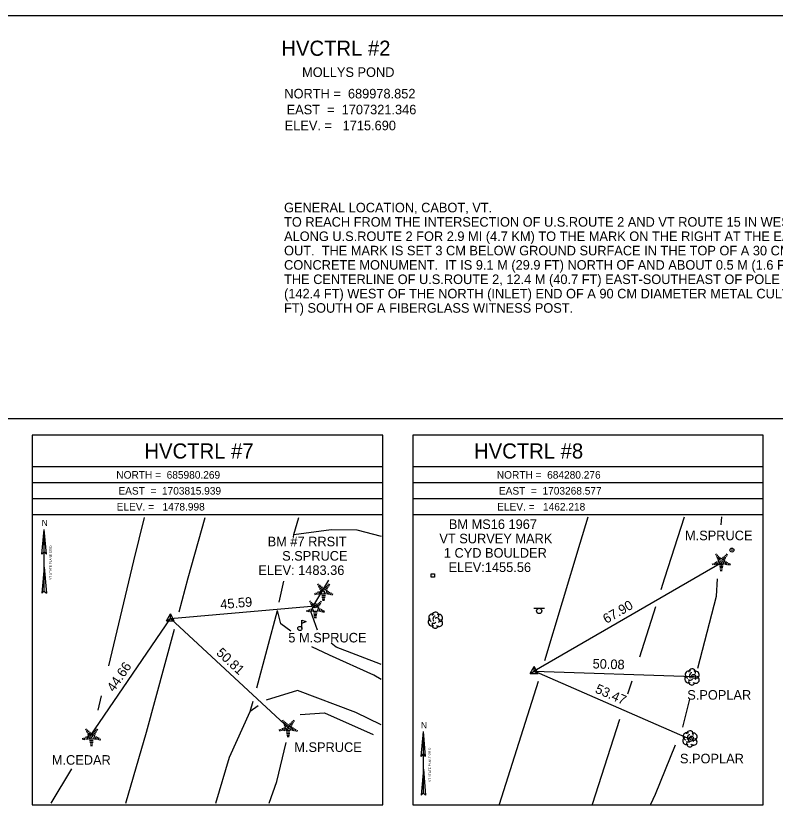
# Model space of a CAD drawing. Extents: x 1702290 to 1703620, y 686233 to 686653.
# Drawn here: x 1702560.6 to 1702798.8, y 686402.8 to 686652.9 of the extents above; entities that cross this region are included whole.
import ezdxf

# ---------------------------------------------------------------- set-up
doc = ezdxf.new("R2010")
doc.units = 0
for name, color, linetype in [('C_C', 7, 'Continuous'), ('CBP', 7, 'Continuous'), ('CPBM', 7, 'Continuous'), ('CPSM', 7, 'Continuous'), ('Default', 7, 'Continuous'), ('L_C', 7, 'Continuous'), ('LAWA', 7, 'Continuous'), ('LMB', 7, 'Continuous'), ('LTC', 7, 'Continuous'), ('LTD', 7, 'Continuous'), ('MPIR', 7, 'Continuous'), ('NBL1', 7, 'Continuous'), ('NBL2', 7, 'Continuous'), ('NNA_P', 7, 'Continuous'), ('PET', 7, 'Continuous'), ('RDG', 7, 'Continuous'), ('RDP', 7, 'Continuous'), ('SSGN', 7, 'Continuous')]:
    doc.layers.add(name, color=color, linetype=linetype)

msp = doc.modelspace()

# ---------------------------------------------------------------- linework, layer by layer
at = {"layer": 'CBP'}
for centre, radius in [((1702782.02, 686481.3), 0.625), ((1702782.02, 686481.3), 0.0833), ((1702654.48, 686467.84), 0.625), ((1702654.48, 686467.84), 0.0833), ((1702773.31, 686445.65), 0.625), ((1702773.31, 686445.65), 0.0833), ((1702646.33, 686429.32), 0.625), ((1702646.33, 686429.32), 0.0833), ((1702583.91, 686426.94), 0.625), ((1702583.91, 686426.94), 0.0833), ((1702772.26, 686425.89), 0.625), ((1702772.26, 686425.89), 0.0833)]:
    msp.add_circle(centre, radius, dxfattribs=at)
at = {"layer": 'CPBM'}
for p, q in [((1702690.96, 686476.81), (1702690.96, 686477.81)), ((1702690.96, 686477.81), (1702691.96, 686477.81)), ((1702691.96, 686477.81), (1702691.96, 686476.81)), ((1702691.96, 686476.81), (1702690.96, 686476.81)), ((1702691.46, 686477.31), (1702691.46, 686477.31)), ((1702691.46, 686477.31), (1702691.46, 686477.31)), ((1702656.32, 686471.5), (1702656.32, 686472.5)), ((1702656.32, 686472.5), (1702657.32, 686472.5)), ((1702657.32, 686471.5), (1702656.32, 686471.5)), ((1702656.83, 686472), (1702656.83, 686472)), ((1702656.83, 686472), (1702656.83, 686472)), ((1702657.32, 686472.5), (1702657.32, 686471.5))]:
    msp.add_line(p, q, dxfattribs=at)
at = {"layer": 'CPSM'}
for p, q in [((1702607.81, 686463.14), (1702609.06, 686465.3)), ((1702610.31, 686463.14), (1702609.06, 686465.3)), ((1702609.06, 686463.86), (1702609.06, 686465.3)), ((1702607.81, 686463.14), (1702609.06, 686463.86)), ((1702607.81, 686463.14), (1702610.31, 686463.14)), ((1702609.06, 686463.86), (1702609.06, 686463.86)), ((1702609.06, 686463.86), (1702610.31, 686463.14)), ((1702722, 686446.56), (1702723.25, 686448.72)), ((1702724.5, 686446.56), (1702723.25, 686448.72)), ((1702723.25, 686447.28), (1702723.25, 686448.72)), ((1702722, 686446.56), (1702723.25, 686447.28)), ((1702722, 686446.56), (1702724.5, 686446.56)), ((1702723.25, 686447.28), (1702723.25, 686447.28)), ((1702723.25, 686447.28), (1702724.5, 686446.56))]:
    msp.add_line(p, q, dxfattribs=at)
at = {"layer": 'Default'}
for p, q in [((1702782.02, 686481.3), (1702723.25, 686447.28)), ((1702609.06, 686463.86), (1702654.48, 686467.84)), ((1702583.91, 686426.94), (1702609.06, 686463.86)), ((1702646.33, 686429.32), (1702609.06, 686463.86)), ((1702723.25, 686447.28), (1702773.31, 686445.65)), ((1702772.26, 686425.89), (1702723.25, 686447.28))]:
    msp.add_line(p, q, dxfattribs=at)
at = {"layer": 'LAWA'}
for points in [[(1702597.61, 686481.91), (1702600.98, 686495.47)], [(1702781.97, 686493.19), (1702782.15, 686495.71)], [(1702589.73, 686448.97), (1702597.61, 686481.91)], [(1702654.04, 686467.99), (1702658.79, 686475.82)], [(1702774.63, 686448.27), (1702780.45, 686470.83), (1702780.82, 686476.26)], [(1702655.29, 686460.14), (1702653.13, 686466.03)], [(1702675.22, 686449.42), (1702675.06, 686449.49), (1702661.06, 686454.83), (1702659.52, 686456.04)], [(1702586.39, 686435.02), (1702587.47, 686439.56)], [(1702769.84, 686429.71), (1702772.12, 686438.57)], [(1702649.79, 686433.68), (1702657.42, 686434.21), (1702672.7, 686427.45)], [(1702640.08, 686405.86), (1702642.46, 686412.67), (1702645.41, 686424.91)], [(1702759.86, 686405.62), (1702761.27, 686408.75), (1702767.6, 686424.22)], [(1702571.67, 686405.86), (1702578.17, 686416.65)]]:
    msp.add_lwpolyline(points, dxfattribs=at)
at = {"layer": 'LMB'}
for p, q in [((1702650.36, 686463.3), (1702651.66, 686462.92)), ((1702650.37, 686460.71), (1702650.37, 686463.3)), ((1702650.37, 686462.4), (1702651.65, 686462.91)), ((1702649.71, 686460.7), (1702649.71, 686460.7))]:
    msp.add_line(p, q, dxfattribs=at)
msp.add_circle((1702649.71, 686460.7), 0.656, dxfattribs=at)
at = {"layer": 'LTC'}
for p, q in [((1702780.09, 686483.85), (1702780.44, 686484.1)), ((1702780.3, 686483.38), (1702780.83, 686483.76)), ((1702780.51, 686482.91), (1702781.21, 686483.43)), ((1702780.72, 686482.45), (1702781.6, 686483.09)), ((1702780.94, 686481.99), (1702781.95, 686482.73)), ((1702781.95, 686482.73), (1702782.95, 686482)), ((1702782.37, 686483.04), (1702783.18, 686482.45)), ((1702782.74, 686483.39), (1702783.42, 686482.9)), ((1702783.12, 686483.74), (1702783.66, 686483.34)), ((1702783.49, 686484.09), (1702783.91, 686483.78)), ((1702779.12, 686481.12), (1702779.27, 686480.66)), ((1702779.58, 686481.34), (1702779.79, 686480.69)), ((1702780.03, 686481.56), (1702780.3, 686480.72)), ((1702780.49, 686481.77), (1702780.82, 686480.76)), ((1702780.94, 686481.99), (1702781.33, 686480.8)), ((1702782.56, 686480.8), (1702781.33, 686480.8)), ((1702782.52, 686480.3), (1702781.38, 686480.3)), ((1702782.95, 686482), (1702782.56, 686480.8)), ((1702783.39, 686481.73), (1702783.05, 686480.69)), ((1702783.83, 686481.48), (1702783.54, 686480.6)), ((1702784.28, 686481.23), (1702784.04, 686480.5)), ((1702784.72, 686480.98), (1702784.53, 686480.41)), ((1702782.44, 686479.8), (1702781.45, 686479.8)), ((1702782.35, 686479.3), (1702781.52, 686479.3)), ((1702782.27, 686478.8), (1702781.59, 686478.8)), ((1702655.29, 686474.48), (1702655.64, 686474.74)), ((1702655.5, 686474.01), (1702656.03, 686474.4)), ((1702655.71, 686473.55), (1702656.41, 686474.06)), ((1702655.92, 686473.08), (1702656.79, 686473.72)), ((1702656.14, 686472.63), (1702657.15, 686473.36)), ((1702657.15, 686473.36), (1702658.15, 686472.64)), ((1702657.57, 686473.68), (1702658.38, 686473.09)), ((1702657.94, 686474.02), (1702658.62, 686473.53)), ((1702658.31, 686474.37), (1702658.86, 686473.97)), ((1702658.69, 686474.72), (1702659.1, 686474.42)), ((1702654.32, 686471.76), (1702654.47, 686471.29)), ((1702654.77, 686471.98), (1702654.99, 686471.32)), ((1702655.23, 686472.19), (1702655.5, 686471.36)), ((1702655.69, 686472.41), (1702656.02, 686471.39)), ((1702656.14, 686472.63), (1702656.53, 686471.43)), ((1702657.76, 686471.43), (1702656.53, 686471.43)), ((1702657.72, 686470.93), (1702656.57, 686470.93)), ((1702657.64, 686470.43), (1702656.65, 686470.43)), ((1702658.15, 686472.64), (1702657.76, 686471.43)), ((1702658.59, 686472.37), (1702658.25, 686471.33)), ((1702659.03, 686472.12), (1702658.74, 686471.23)), ((1702659.48, 686471.87), (1702659.24, 686471.14)), ((1702659.92, 686471.62), (1702659.73, 686471.04)), ((1702652.7, 686469.08), (1702653.06, 686469.33)), ((1702652.91, 686468.61), (1702653.44, 686469)), ((1702653.12, 686468.15), (1702653.83, 686468.66)), ((1702653.33, 686467.68), (1702654.21, 686468.32)), ((1702653.56, 686467.22), (1702654.57, 686467.96)), ((1702654.57, 686467.96), (1702655.57, 686467.23)), ((1702654.99, 686468.27), (1702655.8, 686467.68)), ((1702655.36, 686468.62), (1702656.04, 686468.13)), ((1702655.73, 686468.97), (1702656.28, 686468.57)), ((1702656.1, 686469.32), (1702656.52, 686469.01)), ((1702657.55, 686469.93), (1702656.72, 686469.93)), ((1702657.47, 686469.43), (1702656.79, 686469.43)), ((1702651.74, 686466.36), (1702651.89, 686465.89)), ((1702652.19, 686466.57), (1702652.4, 686465.92)), ((1702652.65, 686466.79), (1702652.92, 686465.95)), ((1702653.1, 686467.01), (1702653.43, 686465.99)), ((1702653.56, 686467.22), (1702653.95, 686466.03)), ((1702655.18, 686466.03), (1702653.95, 686466.03)), ((1702655.14, 686465.53), (1702653.99, 686465.53)), ((1702655.57, 686467.23), (1702655.18, 686466.03)), ((1702656, 686466.96), (1702655.67, 686465.92)), ((1702656.45, 686466.71), (1702656.16, 686465.83)), ((1702656.89, 686466.46), (1702656.66, 686465.73)), ((1702657.34, 686466.21), (1702657.15, 686465.64)), ((1702655.05, 686465.03), (1702654.07, 686465.03)), ((1702654.97, 686464.53), (1702654.14, 686464.53)), ((1702654.89, 686464.03), (1702654.21, 686464.03)), ((1702644.18, 686431.7), (1702644.53, 686431.96)), ((1702644.38, 686431.23), (1702644.91, 686431.62)), ((1702644.59, 686430.77), (1702645.3, 686431.28)), ((1702644.8, 686430.3), (1702645.68, 686430.94)), ((1702645.03, 686429.85), (1702646.04, 686430.58)), ((1702646.04, 686430.58), (1702647.04, 686429.86)), ((1702646.46, 686430.89), (1702647.27, 686430.31)), ((1702646.83, 686431.24), (1702647.51, 686430.75)), ((1702647.2, 686431.59), (1702647.75, 686431.19)), ((1702647.57, 686431.94), (1702647.99, 686431.64)), ((1702582.45, 686428.97), (1702582.81, 686429.23)), ((1702582.66, 686428.5), (1702583.19, 686428.89)), ((1702582.87, 686428.04), (1702583.57, 686428.55)), ((1702583.08, 686427.57), (1702583.96, 686428.21)), ((1702583.31, 686427.12), (1702584.32, 686427.85)), ((1702584.32, 686427.85), (1702585.31, 686427.13)), ((1702584.74, 686428.16), (1702585.55, 686427.57)), ((1702585.11, 686428.51), (1702585.79, 686428.02)), ((1702585.48, 686428.86), (1702586.03, 686428.46)), ((1702585.85, 686429.21), (1702586.27, 686428.9)), ((1702643.21, 686428.98), (1702643.36, 686428.51)), ((1702643.66, 686429.2), (1702643.87, 686428.54)), ((1702644.12, 686429.41), (1702644.39, 686428.58)), ((1702644.57, 686429.63), (1702644.9, 686428.61)), ((1702645.03, 686429.85), (1702645.42, 686428.65)), ((1702646.65, 686428.65), (1702645.42, 686428.65)), ((1702646.61, 686428.15), (1702645.46, 686428.15)), ((1702646.52, 686427.65), (1702645.54, 686427.65)), ((1702647.04, 686429.86), (1702646.65, 686428.65)), ((1702647.47, 686429.59), (1702647.14, 686428.55)), ((1702647.92, 686429.34), (1702647.63, 686428.45)), ((1702648.36, 686429.09), (1702648.13, 686428.36)), ((1702648.81, 686428.84), (1702648.62, 686428.26)), ((1702581.48, 686426.25), (1702581.64, 686425.78)), ((1702581.94, 686426.46), (1702582.15, 686425.81)), ((1702582.4, 686426.68), (1702582.67, 686425.84)), ((1702582.85, 686426.9), (1702583.18, 686425.88)), ((1702583.31, 686427.12), (1702583.69, 686425.92)), ((1702584.92, 686425.92), (1702583.69, 686425.92)), ((1702584.88, 686425.42), (1702583.74, 686425.42)), ((1702585.31, 686427.13), (1702584.92, 686425.92)), ((1702585.75, 686426.85), (1702585.41, 686425.81)), ((1702586.2, 686426.6), (1702585.91, 686425.72)), ((1702586.64, 686426.35), (1702586.4, 686425.62)), ((1702587.08, 686426.1), (1702586.9, 686425.53)), ((1702646.44, 686427.15), (1702645.61, 686427.15)), ((1702646.36, 686426.65), (1702645.68, 686426.65)), ((1702584.8, 686424.92), (1702583.81, 686424.92)), ((1702584.72, 686424.42), (1702583.89, 686424.42)), ((1702584.63, 686423.92), (1702583.96, 686423.92))]:
    msp.add_line(p, q, dxfattribs=at)
at = {"layer": 'LTD'}
for p, q in [((1702692.21, 686463.35), (1702692.21, 686463.35)), ((1702692.21, 686463.35), (1702692.21, 686463.35)), ((1702772.74, 686445.53), (1702772.74, 686445.53)), ((1702772.74, 686445.53), (1702772.74, 686445.53)), ((1702772.09, 686426.12), (1702772.09, 686426.12)), ((1702772.09, 686426.12), (1702772.09, 686426.12))]:
    msp.add_line(p, q, dxfattribs=at)
for centre in [(1702692.26, 686464.79), (1702772.78, 686446.96), (1702772.14, 686427.55)]:
    msp.add_arc(centre, 1.05, 335.5272, 180.9563, dxfattribs=at)
for centre, major_axis, ratio, start_param, end_param in [((1702691.42, 686464.02), (1.21, -0.51), 0.895232, 1.570796, 4.712389), ((1702693.26, 686463.94), (-1.14, -0.48), 0.949671, 1.570796, 4.712389), ((1702691.13, 686462.65), (0.58, -1.04), 0.959034, 3.141593, 6.283185), ((1702691.76, 686462.6), (-0.625, -0.083), 0.423636, 0, 3.141593), ((1702692.01, 686463.81), (-0.208, -0.792), 0.645439, 3.141593, 6.283185), ((1702692.71, 686463.19), (-0.5, 0.667), 0.989748, 3.141593, 6.283185), ((1702693.21, 686462.52), (-1.09, 0.79), 0.841452, 1.570796, 4.712389), ((1702692.21, 686461.85), (0.26, 1.06), 0.942809, 1.570796, 4.712389), ((1702771.65, 686444.82), (0.58, -1.04), 0.959034, 3.141593, 6.283185), ((1702771.94, 686446.2), (1.21, -0.51), 0.895232, 1.570796, 4.712389), ((1702772.53, 686445.99), (-0.208, -0.792), 0.645439, 3.141593, 6.283185), ((1702773.24, 686445.36), (-0.5, 0.667), 0.989748, 3.141593, 6.283185), ((1702773.74, 686444.7), (-1.09, 0.79), 0.841452, 1.570796, 4.712389), ((1702773.78, 686446.11), (-1.14, -0.48), 0.949671, 1.570796, 4.712389), ((1702772.74, 686444.03), (0.26, 1.06), 0.942809, 1.570796, 4.712389), ((1702772.28, 686444.78), (-0.625, -0.083), 0.423636, 0, 3.141593), ((1702771.3, 686426.79), (1.21, -0.51), 0.895232, 1.570796, 4.712389), ((1702773.13, 686426.7), (-1.14, -0.48), 0.949671, 1.570796, 4.712389), ((1702771.01, 686425.41), (0.58, -1.04), 0.959034, 3.141593, 6.283185), ((1702771.63, 686425.37), (-0.625, -0.083), 0.423636, 0, 3.141593), ((1702771.88, 686426.58), (-0.208, -0.792), 0.645439, 3.141593, 6.283185), ((1702772.59, 686425.95), (-0.5, 0.667), 0.989748, 3.141593, 6.283185), ((1702773.09, 686425.29), (-1.09, 0.79), 0.841452, 1.570796, 4.712389), ((1702772.09, 686424.62), (0.26, 1.06), 0.942809, 1.570796, 4.712389)]:
    msp.add_ellipse(centre, major_axis=major_axis, ratio=ratio, start_param=start_param, end_param=end_param, dxfattribs=at)
at = {"layer": 'MPIR'}
for radius in [0.625, 0.0833]:
    msp.add_circle((1702785.29, 686485.29), radius, dxfattribs=at)
at = {"layer": 'NBL1'}
for p, q in [((1702675.72, 686511.4), (1702565.72, 686511.4)), ((1702675.72, 686511.4), (1702565.72, 686511.4)), ((1702795.13, 686511.4), (1702685.13, 686511.4)), ((1702675.72, 686506.4), (1702565.72, 686506.4)), ((1702675.72, 686506.4), (1702565.72, 686506.4)), ((1702795.13, 686506.4), (1702685.13, 686506.4)), ((1702675.72, 686501.4), (1702565.72, 686501.4)), ((1702675.72, 686501.4), (1702565.72, 686501.4)), ((1702795.13, 686501.4), (1702685.13, 686501.4)), ((1702675.72, 686496.4), (1702565.72, 686496.4)), ((1702675.72, 686496.4), (1702565.72, 686496.4)), ((1702795.13, 686496.4), (1702685.13, 686496.4))]:
    msp.add_line(p, q, dxfattribs=at)
for points in [[(1702290.49, 686232.9), (1702930.49, 686232.9), (1702930.49, 686652.9), (1702290.49, 686652.9)], [(1702565.72, 686405.4), (1702675.72, 686405.4), (1702675.72, 686521.4), (1702565.72, 686521.4)], [(1702565.72, 686405.4), (1702675.72, 686405.4), (1702675.72, 686521.4), (1702565.72, 686521.4)], [(1702685.13, 686405.4), (1702795.13, 686405.4), (1702795.13, 686521.4), (1702685.13, 686521.4)]]:
    msp.add_lwpolyline(points, close=True, dxfattribs=at)
at = {"layer": 'NBL2'}
msp.add_line((1702290.49, 686526.56), (1702930.49, 686526.56), dxfattribs=at)
at = {"layer": 'NNA_P'}
for p, q in [((1702568.78, 686484), (1702569.48, 686491.79)), ((1702569.48, 686472.42), (1702569.48, 686491.79)), ((1702570.17, 686484), (1702569.48, 686491.79)), ((1702568.78, 686484), (1702569.48, 686484.77)), ((1702570.17, 686484), (1702569.48, 686484.77)), ((1702569.48, 686479.94), (1702568.76, 686471.78)), ((1702569.48, 686479.94), (1702570.2, 686471.78)), ((1702569.48, 686472.42), (1702568.76, 686471.78)), ((1702569.48, 686472.42), (1702570.2, 686471.78)), ((1702687.76, 686420.58), (1702688.46, 686428.37)), ((1702688.46, 686408.99), (1702688.46, 686428.37)), ((1702689.15, 686420.58), (1702688.46, 686428.37)), ((1702687.76, 686420.58), (1702688.46, 686421.34)), ((1702689.15, 686420.58), (1702688.46, 686421.34)), ((1702688.46, 686416.52), (1702687.74, 686408.35)), ((1702688.46, 686416.52), (1702689.18, 686408.35)), ((1702688.46, 686408.99), (1702687.74, 686408.35)), ((1702688.46, 686408.99), (1702689.18, 686408.35))]:
    msp.add_line(p, q, dxfattribs=at)
at = {"layer": 'PET'}
for points in [[(1702611.79, 686465.87), (1702614.68, 686476.58), (1702619.99, 686495.47)], [(1702647.67, 686489.39), (1702647.84, 686490.18), (1702649.43, 686495.47)], [(1702726.57, 686450.7), (1702737.7, 686487.42), (1702740.17, 686495.71)], [(1702763.1, 686472.96), (1702764.27, 686476.64), (1702770.41, 686495.71)], [(1702643.21, 686468.96), (1702644.65, 686475.56)], [(1702636.16, 686442.07), (1702642.65, 686466.37)], [(1702756.38, 686451.83), (1702761.4, 686467.63)], [(1702595.07, 686405.86), (1702601.6, 686428.18), (1702610.34, 686460.53)], [(1702712.37, 686405.62), (1702724.57, 686444.12)], [(1702752.67, 686440.15), (1702753.99, 686444.3)], [(1702623.37, 686405.86), (1702627.67, 686420.35), (1702634.16, 686434.61), (1702635.03, 686437.85)], [(1702741.56, 686405.62), (1702750.14, 686432.27)]]:
    msp.add_lwpolyline(points, dxfattribs=at)
at = {"layer": 'RDG'}
msp.add_lwpolyline([(1702647.84, 686490.18), (1702659.48, 686491.74), (1702667.56, 686491.67), (1702675.22, 686489.62)], dxfattribs=at)
at = {"layer": 'RDP'}
for points in [[(1702646.86, 686459.87), (1702643.72, 686462.2), (1702642.65, 686466.37)], [(1702675.22, 686444.65), (1702672.96, 686446.01), (1702659.01, 686452.36), (1702653.46, 686454.98)], [(1702675.22, 686430.48), (1702667.29, 686434.29), (1702648.94, 686441.28), (1702639.15, 686438.18)], [(1702636.66, 686436.39), (1702634.16, 686434.61)]]:
    msp.add_lwpolyline(points, dxfattribs=at)
at = {"layer": 'SSGN'}
for p, q in [((1702723.15, 686467.03), (1702726.48, 686467.03)), ((1702724.8, 686466.2), (1702724.8, 686466.2))]:
    msp.add_line(p, q, dxfattribs=at)
msp.add_circle((1702724.8, 686466.2), 0.833, dxfattribs=at)

# ---------------------------------------------------------------- texts
at = {"layer": 'C_C'}
for s, p in [('BM #7 RRSIT', (1702639.61, 686486.49)), ('S.SPRUCE', (1702644.15, 686481.99)), ('ELEV: 1483.36', (1702636.69, 686477.49))]:
    msp.add_text(s, height=3, dxfattribs=at).set_placement(p)
at = {"layer": 'Default'}
for s, p in [('GENERAL LOCATION, CABOT, VT.  ', (1702644.75, 686591.27)), ('TO REACH FROM THE INTERSECTION OF U.S.ROUTE 2 AND VT ROUTE 15 IN WEST DANVILLE GO WEST ', (1702644.75, 686586.77)), ('ALONG U.S.ROUTE 2 FOR 2.9 MI (4.7 KM) TO THE MARK ON THE RIGHT AT THE EAST END OF A PULL ', (1702644.75, 686582.27)), ('OUT.  THE MARK IS SET 3 CM BELOW GROUND SURFACE IN THE TOP OF A 30 CM (12")DIAMETER ', (1702644.75, 686577.77)), ('CONCRETE MONUMENT.  IT IS 9.1 M (29.9 FT) NORTH OF AND ABOUT 0.5 M (1.6 FT) LOWER THAN ', (1702644.75, 686573.27)), ('THE CENTERLINE OF U.S.ROUTE 2, 12.4 M (40.7 FT) EAST-SOUTHEAST OF POLE NO.83, 43.4 M ', (1702644.75, 686568.77)), ('(142.4 FT) WEST OF THE NORTH (INLET) END OF A 90 CM DIAMETER METAL CULVERT, 0.8 M (2.6 ', (1702644.75, 686564.27)), ('FT) SOUTH OF A FIBERGLASS WITNESS POST. ', (1702644.75, 686559.77))]:
    msp.add_text(s, height=3, dxfattribs=at).set_placement(p)
for s, rotation, p in [('45.59', 5.0034, (1702624.86, 686466.75)), ('67.90', 30.0707, (1702745.9, 686462.12)), ('50.81', 317.1795, (1702623.26, 686452.75)), ('44.66', 55.7335, (1702591.37, 686440.57)), ('50.08', 358.1409, (1702741.54, 686448.18)), ('53.47', 336.4203, (1702742.13, 686440.67))]:
    msp.add_text(s, height=3, rotation=rotation, dxfattribs=at).set_placement(p)
at = {"layer": 'L_C'}
for s, p in [('BM MS16 1967', (1702696.46, 686491.92)), ('VT SURVEY MARK', (1702693.49, 686487.42)), ('M.SPRUCE', (1702770.57, 686488.39)), ('1 CYD BOULDER', (1702694.89, 686482.92)), ('ELEV:1455.56', (1702696.38, 686478.42)), ('5 M.SPRUCE', (1702646.09, 686456.32)), ('S.POPLAR', (1702771.28, 686438.36)), ('M.SPRUCE', (1702647.96, 686421.96)), ('M.CEDAR', (1702571.87, 686417.95)), ('S.POPLAR', (1702768.98, 686418.38))]:
    msp.add_text(s, height=3, dxfattribs=at).set_placement(p)
at = {"layer": 'LTC'}
for p in [(1702781.84, 686481.74), (1702657.03, 686472.38), (1702654.45, 686466.97), (1702645.92, 686429.6), (1702584.2, 686426.86)]:
    msp.add_text('.', height=1.04, rotation=270, dxfattribs=at).set_placement(p)
at = {"layer": 'NBL1'}
msp.add_text('HVCTRL #7', height=4.75, dxfattribs=at).set_placement((1702600.94, 686514.02))
at = {"layer": 'NBL2'}
for s, height, p in [('     HVCTRL #2     ', 4.75, (1702635.07, 686640.39)), ('     MOLLYS POND    ', 3, (1702644.84, 686633.76)), ('NORTH =  689978.852 ', 3, (1702644.84, 686627.02)), ('EAST  =  1707321.346', 3, (1702645.55, 686622.02)), ('ELEV. =   1715.690  ', 3, (1702644.95, 686617.02)), ('     HVCTRL #8     ', 4.75, (1702695.55, 686514.02)), ('NORTH =  685980.269 ', 2.375, (1702592.11, 686507.71)), ('NORTH =  684280.276 ', 2.375, (1702711.52, 686507.71)), ('EAST  =  1703815.939', 2.375, (1702592.76, 686502.71)), ('EAST  =  1703268.577', 2.375, (1702712.18, 686502.71)), ('ELEV. =   1478.998  ', 2.375, (1702592.22, 686497.71)), ('ELEV. =   1462.218  ', 2.375, (1702711.63, 686497.71))]:
    msp.add_text(s, height=height, dxfattribs=at).set_placement(p)
at = {"layer": 'NNA_P'}
for p in [(1702568.71, 686492.81), (1702687.7, 686429.38)]:
    msp.add_text('N', height=1.97, dxfattribs=at).set_placement(p)
for p in [(1702571.83, 686475.98), (1702690.81, 686412.56)]:
    msp.add_text('VT STATE PLANE GRID', height=0.7, rotation=90.0204, dxfattribs=at).set_placement(p)

doc.saveas('drawing.dxf')
